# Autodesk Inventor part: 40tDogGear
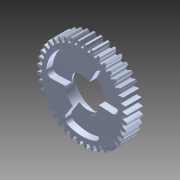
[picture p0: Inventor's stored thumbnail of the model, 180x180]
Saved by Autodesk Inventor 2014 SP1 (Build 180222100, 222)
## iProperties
Created: 2014-11
Part Number: 40tDogGear
Material: Aluminum 6061
Document SubType Name: Modeling
Designer: Michael
Density: 2.71 g/cm^3
Appearance: Aluminum - Flat
Title: 217-3417-STEP.STEP
Description: STEP AP214
Creation Date: 2013-12-09
Sending System: SolidWorks 2013
Preprocessor: SwSTEP 2.0
Author: Michael
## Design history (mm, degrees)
node "40tDogGear1"
node "BackBore"
node "Base1"
